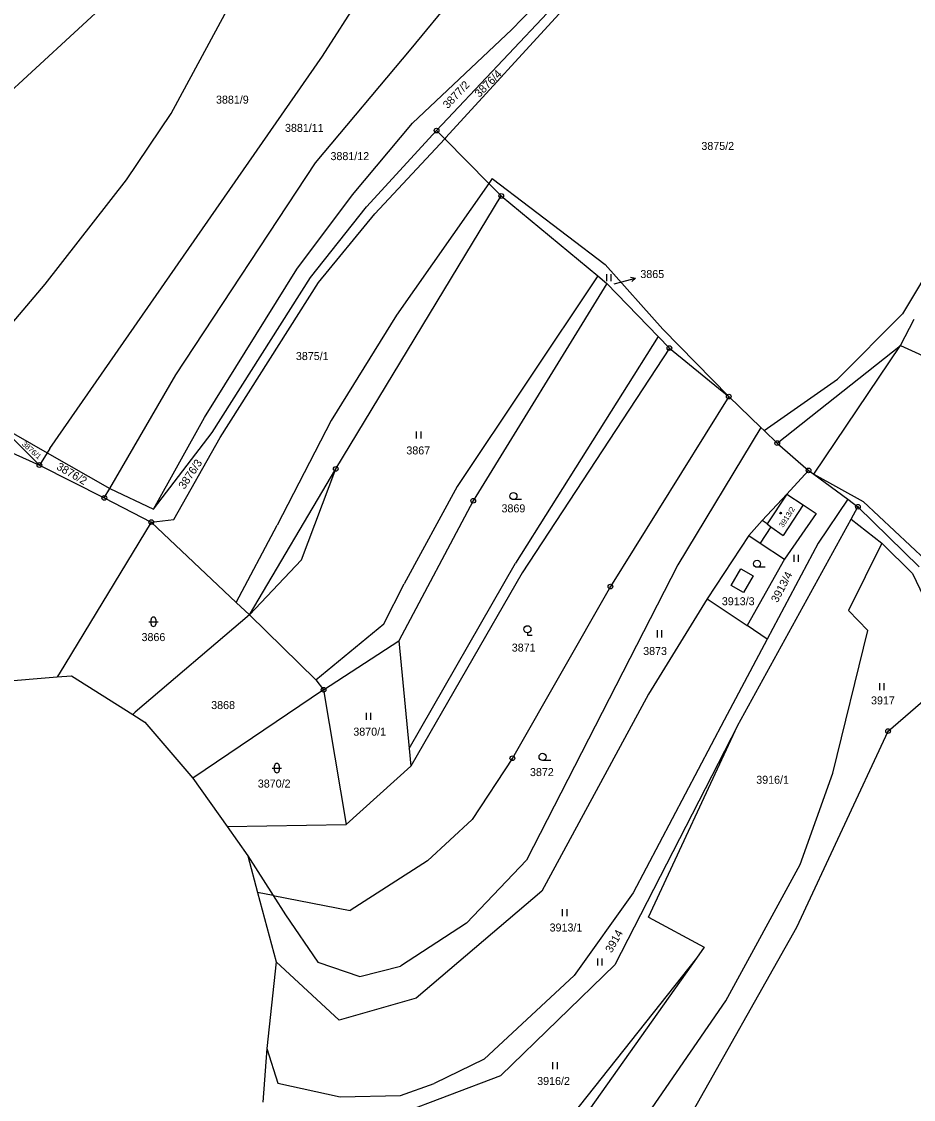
# Model space of a CAD drawing. Extents: x -593183 to -588034, y -1130415 to -1124994.
# Drawn here: x -592655.1 to -592465.6, y -1130104.5 to -1129875.5 of the extents above; entities that cross this region are included whole.
import ezdxf

# ---------------------------------------------------------------- set-up
doc = ezdxf.new("R2010")
doc.units = 0
for name, color, linetype in [('Vrstva 1', 7, 'Continuous'), ('Vrstva 13', 7, 'Continuous'), ('Vrstva 16', 7, 'Continuous'), ('Vrstva 18', 7, 'Continuous'), ('Vrstva 19', 7, 'Continuous'), ('Vrstva 24', 7, 'Continuous'), ('Vrstva 25', 7, 'Continuous'), ('Vrstva 4', 7, 'Continuous')]:
    doc.layers.add(name, color=color, linetype=linetype)

msp = doc.modelspace()

# ---------------------------------------------------------------- linework, layer by layer
at = {"layer": 'Vrstva 1'}
for p, q in [((-592599.9, -1129837.26), (-592687.44, -1129917.94)), ((-592623.34, -1129895.04), (-592595.29, -1129842.99)), ((-592591.16, -1129882.85), (-592568.03, -1129846.5)), ((-592572.35, -1129881.29), (-592556.14, -1129861.51)), ((-592550.96, -1129877.13), (-592543.61, -1129869.53)), ((-592566.96, -1129898.63), (-592541.07, -1129871.15)), ((-592564.95, -1129900.07), (-592539.38, -1129872.23)), ((-592572.03, -1129897.06), (-592550.96, -1129877.13)), ((-592592.7, -1129905.51), (-592572.35, -1129881.29)), ((-592649.12, -1129966.18), (-592591.16, -1129882.85)), ((-592632.82, -1129909.11), (-592623.34, -1129895.04)), ((-592584.78, -1129912.29), (-592572.03, -1129897.06)), ((-592581.82, -1129914.83), (-592566.96, -1129898.63)), ((-592566.96, -1129898.63), (-592565.23, -1129900.38)), ((-592565.23, -1129900.38), (-592580.07, -1129916.32)), ((-592564.95, -1129900.07), (-592565.23, -1129900.38)), ((-592565.23, -1129900.38), (-592555.86, -1129909.86)), ((-592622.35, -1129950.52), (-592592.7, -1129905.51)), ((-592650.14, -1129931.24), (-592632.82, -1129909.11)), ((-592555.13, -1129908.81), (-592555.86, -1129909.86)), ((-592555.13, -1129908.81), (-592531.1, -1129927.09)), ((-592555.86, -1129909.86), (-592575.48, -1129937.87)), ((-592555.86, -1129909.86), (-592553.22, -1129912.53)), ((-592596.65, -1129928.08), (-592584.78, -1129912.29)), ((-592588.38, -1129970.52), (-592553.22, -1129912.53)), ((-592553.22, -1129912.53), (-592532.7, -1129929.49)), ((-592593.76, -1129929.88), (-592581.82, -1129914.83)), ((-592592.07, -1129930.93), (-592580.07, -1129916.32)), ((-592459.82, -1129923.96), (-592467.98, -1129937.58)), ((-592531.1, -1129927.09), (-592518.9, -1129940.81)), ((-592616.24, -1129959.57), (-592596.65, -1129928.08)), ((-592532.7, -1129929.49), (-592562.54, -1129974.28)), ((-592532.7, -1129929.49), (-592530.76, -1129931.09)), ((-592667.99, -1129952.37), (-592650.14, -1129931.24)), ((-592614.64, -1129962.79), (-592593.76, -1129929.88)), ((-592612.95, -1129963.86), (-592592.07, -1129930.93)), ((-592530.76, -1129931.09), (-592559.15, -1129977.27)), ((-592530.76, -1129931.09), (-592519.88, -1129942.36)), ((-592575.48, -1129937.87), (-592589.38, -1129960.21)), ((-592467.98, -1129937.58), (-592481.74, -1129951.44)), ((-592468.34, -1129944.33), (-592465.45, -1129938.69)), ((-592504.85, -1129955.16), (-592518.9, -1129940.81)), ((-592519.88, -1129942.36), (-592550.18, -1129990.54)), ((-592519.88, -1129942.36), (-592517.48, -1129944.84)), ((-592517.48, -1129944.84), (-592548.78, -1129992.61)), ((-592517.48, -1129944.84), (-592506.26, -1129954)), ((-592494.55, -1129965.04), (-592468.34, -1129944.33)), ((-592468.34, -1129944.33), (-592442.22, -1129956.15)), ((-592636.4, -1129974.7), (-592622.35, -1129950.52)), ((-592497.31, -1129962.39), (-592481.74, -1129951.44)), ((-592506.26, -1129954), (-592504.85, -1129955.16)), ((-592504.85, -1129955.16), (-592530.01, -1129995.52)), ((-592498.03, -1129961.71), (-592504.85, -1129955.16)), ((-592659.66, -1129961.35), (-592651.34, -1129969.69)), ((-592659.66, -1129961.35), (-592649.69, -1129967.07)), ((-592627.08, -1129979.08), (-592616.24, -1129959.57)), ((-592589.38, -1129960.21), (-592600.85, -1129982.44)), ((-592498.03, -1129961.71), (-592515.68, -1129990.9)), ((-592497.31, -1129962.39), (-592498.03, -1129961.71)), ((-592627.08, -1129979.08), (-592614.64, -1129962.79)), ((-592622.81, -1129981.29), (-592612.95, -1129963.86)), ((-592497.31, -1129962.39), (-592494.55, -1129965.04)), ((-592649.12, -1129966.18), (-592649.69, -1129967.07)), ((-592494.55, -1129965.04), (-592487.91, -1129970.83)), ((-592649.69, -1129967.07), (-592651.34, -1129969.69)), ((-592649.69, -1129967.07), (-592636.4, -1129974.7)), ((-592651.34, -1129969.69), (-592637.55, -1129976.69)), ((-592606.71, -1130001.54), (-592588.38, -1129970.52)), ((-592487.91, -1129970.83), (-592492.53, -1129975.87)), ((-592487.91, -1129970.83), (-592486.78, -1129971.66)), ((-592486.78, -1129971.66), (-592479.58, -1129976.95)), ((-592486.78, -1129971.66), (-592476.29, -1129977.41)), ((-592637.55, -1129976.69), (-592636.4, -1129974.7)), ((-592636.4, -1129974.7), (-592627.08, -1129979.08)), ((-592562.54, -1129974.28), (-592573.87, -1129994.93)), ((-592637.55, -1129976.69), (-592627.57, -1129981.81)), ((-592559.15, -1129977.27), (-592574.96, -1130007.04)), ((-592492.53, -1129975.87), (-592497.74, -1129981.49)), ((-592492.53, -1129975.87), (-592489.05, -1129978.17)), ((-592479.58, -1129976.95), (-592485.9, -1129986.31)), ((-592479.58, -1129976.95), (-592477.41, -1129978.55)), ((-592476.29, -1129977.41), (-592462.99, -1129989.9)), ((-592486.32, -1129979.98), (-592493.03, -1129989.69)), ((-592489.05, -1129978.17), (-592486.32, -1129979.98)), ((-592478.87, -1129981.2), (-592477.41, -1129978.55)), ((-592477.41, -1129978.55), (-592464.39, -1129991.33)), ((-592627.57, -1129981.81), (-592647.12, -1130014.03)), ((-592627.57, -1129981.81), (-592622.81, -1129981.29)), ((-592627.57, -1129981.81), (-592609.5, -1129998.9)), ((-592503.01, -1130025.09), (-592478.87, -1129981.2)), ((-592497.74, -1129981.49), (-592500.63, -1129984.69)), ((-592478.87, -1129981.2), (-592472.31, -1129986.26)), ((-592609.5, -1129998.9), (-592600.85, -1129982.44)), ((-592500.63, -1129984.69), (-592509.42, -1129998.15)), ((-592500.63, -1129984.69), (-592498.19, -1129986.3)), ((-592498.19, -1129986.3), (-592493.03, -1129989.69)), ((-592485.9, -1129986.31), (-592496.7, -1130006.66)), ((-592472.31, -1129986.26), (-592479.45, -1130000.63)), ((-592572.79, -1130029.93), (-592550.18, -1129990.54)), ((-592515.68, -1129990.9), (-592547.87, -1130053.63)), ((-592493.03, -1129989.69), (-592500.95, -1130003.82)), ((-592548.78, -1129992.61), (-592572.44, -1130033.65)), ((-592578.14, -1130003.4), (-592573.87, -1129994.93)), ((-592530.01, -1129995.52), (-592550.85, -1130032)), ((-592509.42, -1129998.15), (-592521.92, -1130018.41)), ((-592509.42, -1129998.15), (-592500.95, -1130003.82)), ((-592479.45, -1130000.63), (-592475.31, -1130004.85)), ((-592606.71, -1130001.54), (-592630.98, -1130022.23)), ((-592606.71, -1130001.54), (-592592.64, -1130015.32)), ((-592592.64, -1130015.32), (-592578.14, -1130003.4)), ((-592496.7, -1130006.66), (-592500.95, -1130003.82)), ((-592482.77, -1130035.16), (-592475.31, -1130004.85)), ((-592590.96, -1130017.45), (-592574.96, -1130007.04)), ((-592574.96, -1130007.04), (-592572.79, -1130029.93)), ((-592496.7, -1130006.66), (-592505.83, -1130023.87)), ((-592647.12, -1130014.03), (-592647.54, -1130014.72)), ((-592471.02, -1130026.21), (-592456.08, -1130013.33)), ((-592590.96, -1130017.45), (-592618.74, -1130036.2)), ((-592590.96, -1130017.45), (-592586.18, -1130046.05)), ((-592521.92, -1130018.41), (-592544.55, -1130060.2)), ((-592631.52, -1130022.69), (-592630.98, -1130022.23)), ((-592503.01, -1130025.09), (-592529.06, -1130075.89)), ((-592505.83, -1130023.87), (-592525.15, -1130060.6)), ((-592521.91, -1130065.76), (-592503.01, -1130025.09)), ((-592490.37, -1130067.86), (-592471.02, -1130026.21)), ((-592550.85, -1130032), (-592559.39, -1130044.97)), ((-592586.18, -1130046.05), (-592572.44, -1130033.65)), ((-592489.67, -1130054.54), (-592482.77, -1130035.16)), ((-592611.45, -1130046.52), (-592586.18, -1130046.05)), ((-592559.39, -1130044.97), (-592568.88, -1130053.75)), ((-592568.88, -1130053.75), (-592585.3, -1130064.34)), ((-592547.87, -1130053.63), (-592560.56, -1130067.04)), ((-592505.5, -1130083.53), (-592489.67, -1130054.54)), ((-592544.55, -1130060.2), (-592571.3, -1130082.93)), ((-592601.69, -1130061.13), (-592604.98, -1130060.49)), ((-592601.69, -1130061.13), (-592585.3, -1130064.34)), ((-592601.69, -1130061.13), (-592599.04, -1130065.27)), ((-592525.15, -1130060.6), (-592537.73, -1130078.17)), ((-592599.04, -1130065.27), (-592592.19, -1130075.34)), ((-592560.56, -1130067.04), (-592574.63, -1130076.13)), ((-592521.91, -1130065.76), (-592510.09, -1130072.13)), ((-592515.94, -1130113.03), (-592490.37, -1130067.86)), ((-592510.09, -1130072.13), (-592511.75, -1130074.44)), ((-592587.63, -1130087.62), (-592601, -1130075.24)), ((-592592.19, -1130075.34), (-592583.24, -1130078.37)), ((-592583.24, -1130078.37), (-592574.63, -1130076.13)), ((-592553.28, -1130099.41), (-592529.06, -1130075.89)), ((-592511.75, -1130074.44), (-592551.81, -1130125)), ((-592511.75, -1130074.44), (-592546.8, -1130123.9)), ((-592537.73, -1130078.17), (-592556.83, -1130095.9)), ((-592571.3, -1130082.93), (-592587.63, -1130087.62)), ((-592525.69, -1130112.83), (-592505.5, -1130083.53)), ((-592603, -1130093.66), (-592600.66, -1130101.02)), ((-592556.83, -1130095.9), (-592567.46, -1130101.08)), ((-592600.66, -1130101.02), (-592587.46, -1130103.93)), ((-592574.94, -1130107.63), (-592553.28, -1130099.41)), ((-592574.59, -1130103.65), (-592567.46, -1130101.08)), ((-592587.46, -1130103.93), (-592574.59, -1130103.65))]:
    msp.add_line(p, q, dxfattribs=at)
at = {"layer": 'Vrstva 13'}
for p, q in [((-592660.55, -1130015.81), (-592647.54, -1130014.72)), ((-592647.54, -1130014.72), (-592644.51, -1130014.47)), ((-592644.51, -1130014.47), (-592631.52, -1130022.69)), ((-592631.52, -1130022.69), (-592628.96, -1130024.31)), ((-592628.96, -1130024.31), (-592618.74, -1130036.2)), ((-592618.74, -1130036.2), (-592611.45, -1130046.52)), ((-592611.45, -1130046.52), (-592607.09, -1130052.69)), ((-592607.09, -1130052.69), (-592604.98, -1130060.49)), ((-592604.98, -1130060.49), (-592601, -1130075.24)), ((-592601, -1130075.24), (-592603, -1130093.66)), ((-592603, -1130093.66), (-592603.85, -1130105.03))]:
    msp.add_line(p, q, dxfattribs=at)
at = {"layer": 'Vrstva 16'}
msp.add_line((-592529.23, -1129931.2), (-592527.55, -1129930.75), dxfattribs=at)
at = {"layer": 'Vrstva 24'}
for centre, radius in [((-592566.96, -1129898.63), 0.5), ((-592566.96, -1129898.63), 0.0327), ((-592553.22, -1129912.53), 0.5), ((-592553.22, -1129912.53), 0.0327), ((-592517.48, -1129944.84), 0.5), ((-592517.48, -1129944.84), 0.0327), ((-592504.85, -1129955.16), 0.5), ((-592504.85, -1129955.16), 0.0327), ((-592494.55, -1129965.04), 0.5), ((-592494.55, -1129965.04), 0.0327), ((-592651.34, -1129969.69), 0.5), ((-592651.34, -1129969.69), 0.0327), ((-592588.38, -1129970.52), 0.5), ((-592588.38, -1129970.52), 0.0327), ((-592487.91, -1129970.83), 0.5), ((-592487.91, -1129970.83), 0.0327), ((-592637.55, -1129976.69), 0.5), ((-592637.55, -1129976.69), 0.0327), ((-592559.15, -1129977.27), 0.5), ((-592559.15, -1129977.27), 0.0327), ((-592477.41, -1129978.55), 0.5), ((-592477.41, -1129978.55), 0.0327), ((-592627.57, -1129981.81), 0.5), ((-592627.57, -1129981.81), 0.0327), ((-592530.01, -1129995.52), 0.5), ((-592530.01, -1129995.52), 0.0327), ((-592590.96, -1130017.45), 0.5), ((-592590.96, -1130017.45), 0.0327), ((-592471.02, -1130026.21), 0.5), ((-592471.02, -1130026.21), 0.0327), ((-592550.85, -1130032), 0.5), ((-592550.85, -1130032), 0.0327)]:
    msp.add_circle(centre, radius, dxfattribs=at)
at = {"layer": 'Vrstva 25'}
for p, q in [((-592530.87, -1129929.11), (-592530.87, -1129930.61)), ((-592529.84, -1129930.61), (-592529.84, -1129929.11)), ((-592527.55, -1129930.75), (-592524.65, -1129929.97)), ((-592571.26, -1129962.58), (-592571.26, -1129964.08)), ((-592570.23, -1129964.08), (-592570.23, -1129962.58)), ((-592548.87, -1129977.05), (-592550.62, -1129977.05)), ((-592491.07, -1129988.79), (-592491.07, -1129990.29)), ((-592490.05, -1129990.29), (-592490.05, -1129988.79)), ((-592497.1, -1129991.42), (-592498.85, -1129991.42)), ((-592628.12, -1130003), (-592626.12, -1130003)), ((-592627.62, -1130003.5), (-592627.62, -1130002.5)), ((-592626.62, -1130002.5), (-592626.62, -1130003.5)), ((-592520.07, -1130004.81), (-592520.07, -1130006.31)), ((-592519.05, -1130006.31), (-592519.05, -1130004.81)), ((-592547.64, -1130005.33), (-592547.64, -1130005.83)), ((-592547.64, -1130005.83), (-592546.62, -1130005.83)), ((-592472.86, -1130016.03), (-592472.86, -1130017.53)), ((-592471.84, -1130017.53), (-592471.84, -1130016.03)), ((-592581.94, -1130022.31), (-592581.94, -1130023.81)), ((-592580.92, -1130023.81), (-592580.92, -1130022.31)), ((-592542.68, -1130032.44), (-592544.43, -1130032.44)), ((-592601.87, -1130034.08), (-592599.87, -1130034.08)), ((-592601.37, -1130034.58), (-592601.37, -1130033.58)), ((-592600.37, -1130033.58), (-592600.37, -1130034.58)), ((-592540.24, -1130064.06), (-592540.24, -1130065.56)), ((-592539.22, -1130065.56), (-592539.22, -1130064.06)), ((-592532.77, -1130074.52), (-592532.77, -1130076.02)), ((-592531.74, -1130076.02), (-592531.74, -1130074.52)), ((-592542.3, -1130096.55), (-592542.3, -1130098.05)), ((-592541.28, -1130098.05), (-592541.28, -1130096.55))]:
    msp.add_line(p, q, dxfattribs=at)
msp.add_lwpolyline([(-592525.75, -1129929.75), (-592524.65, -1129929.97), (-592525.49, -1129930.71)], dxfattribs=at)
for centre, radius in [((-592550.62, -1129976.3), 0.75), ((-592493.84, -1129979.91), 0.175), ((-592493.84, -1129979.91), 0.15), ((-592498.85, -1129990.67), 0.75), ((-592547.64, -1130004.58), 0.75), ((-592544.43, -1130031.69), 0.75)]:
    msp.add_circle(centre, radius, dxfattribs=at)
for centre, start, end in [((-592627.12, -1130002.5), 90, 180), ((-592627.12, -1130002.5), 0, 90), ((-592627.12, -1130003.5), 180, 270), ((-592627.12, -1130003.5), 270, 0), ((-592600.87, -1130033.58), 90, 180), ((-592600.87, -1130034.58), 180, 270), ((-592600.87, -1130033.58), 0, 90), ((-592600.87, -1130034.58), 270, 0)]:
    msp.add_arc(centre, 0.5, start, end, dxfattribs=at)
at = {"layer": 'Vrstva 4'}
for p, q in [((-592486.78, -1129971.66), (-592468.34, -1129944.33)), ((-592658.52, -1129966.44), (-592651.34, -1129969.69)), ((-592595.67, -1129989.86), (-592588.38, -1129970.52)), ((-592492.53, -1129975.87), (-592496.72, -1129982.21)), ((-592489.05, -1129978.17), (-592493.32, -1129984.63)), ((-592496.72, -1129982.21), (-592497.74, -1129981.49)), ((-592496.72, -1129982.21), (-592495.89, -1129982.8)), ((-592495.89, -1129982.8), (-592498.19, -1129986.3)), ((-592495.89, -1129982.8), (-592493.32, -1129984.63)), ((-592472.31, -1129986.26), (-592465.79, -1129992.76)), ((-592606.71, -1130001.54), (-592595.67, -1129989.86)), ((-592504.37, -1129995.31), (-592502.3, -1129991.72)), ((-592502.3, -1129991.72), (-592499.67, -1129993.2)), ((-592499.67, -1129993.2), (-592501.73, -1129996.78)), ((-592465.79, -1129992.76), (-592456.08, -1130013.33)), ((-592501.73, -1129996.78), (-592504.37, -1129995.31)), ((-592609.5, -1129998.9), (-592606.71, -1130001.54)), ((-592592.64, -1130015.32), (-592590.96, -1130017.45)), ((-592572.79, -1130029.93), (-592572.44, -1130033.65)), ((-592607.09, -1130052.69), (-592601.69, -1130061.13))]:
    msp.add_line(p, q, dxfattribs=at)

# ---------------------------------------------------------------- texts
at = {"layer": 'Vrstva 16'}
msp.add_text('3865', height=1.7, dxfattribs=at).set_placement((-592523.65, -1129929.97))
at = {"layer": 'Vrstva 18'}
for s, height, rotation, p in [('3876/4', 1.7, 45, (-592557.87, -1129891.71)), ('3877/2', 1.7, 46.5941, (-592564.57, -1129894.11)), ('3876/1', 1.14, 318.3949, (-592655.16, -1129965.38)), ('3876/3', 1.7, 56.0458, (-592620.54, -1129974.97)), ('3876/2', 1.7, 329.9332, (-592647.87, -1129970.5)), ('3913/4', 1.7, 62.231, (-592494.5, -1129999.07)), ('3914', 1.7, 60.8838, (-592529.75, -1130073.47))]:
    msp.add_text(s, height=height, rotation=rotation, dxfattribs=at).set_placement(p)
for s, height, p in [('3881/9', 1.7, (-592613.82, -1129892.91)), ('3881/11', 1.7, (-592599.16, -1129898.91)), ('3875/2', 1.7, (-592510.68, -1129902.75)), ('3881/12', 1.7, (-592589.49, -1129904.91)), ('3865', 0.1, (-592529.23, -1129931.2)), ('3875/1', 1.7, (-592596.84, -1129947.39)), ('3867', 1.7, (-592573.37, -1129967.44)), ('3869', 1.7, (-592553.15, -1129979.75)), ('3913/3', 1.7, (-592506.33, -1129999.48)), ('3866', 1.7, (-592629.64, -1130007.1)), ('3871', 1.7, (-592550.97, -1130009.33)), ('3873', 1.7, (-592523.05, -1130010.05)), ('3917', 1.7, (-592474.63, -1130020.55)), ('3868', 1.7, (-592614.84, -1130021.54)), ('3870/1', 1.7, (-592584.64, -1130027.19)), ('3872', 1.7, (-592547.1, -1130035.78)), ('3870/2', 1.7, (-592604.93, -1130038.22)), ('3916/1', 1.7, (-592499.02, -1130037.41)), ('3913/1', 1.7, (-592542.93, -1130068.8)), ('3916/2', 1.7, (-592545.57, -1130101.41))]:
    msp.add_text(s, height=height, dxfattribs=at).set_placement(p)
at = {"layer": 'Vrstva 19'}
msp.add_text('3913/2', height=1.14, rotation=57.4074, dxfattribs=at).set_placement((-592493.32, -1129983.07))

doc.saveas('drawing.dxf')
